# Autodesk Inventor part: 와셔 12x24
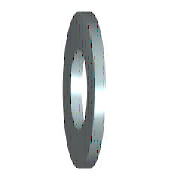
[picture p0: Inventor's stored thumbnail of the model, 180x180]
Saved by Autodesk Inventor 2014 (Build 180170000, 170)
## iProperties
IsCustomPart: 1
Created: 2012-02
Part Number: 와셔 12x24
Material: 스테인리스강
Description: 평면 와셔
Document SubType Name: Modeling
Standard: KS B 1326
Designer: mduedu
Standards Organization: KS
Language: ko-KR
Size Designation: 12x24
Categories: <MemberInstance><Categories><Category DisplayName="조임쇠" InternalName="e4da775c-781d-43d5-af7c-5136215cf5a6" Mnemonic="FSTN"><Category DisplayName="와셔" InternalN
Density: 1 g/cm^3
Appearance: 파란색 - 벽 페인트 - 광택
Author: mduedu
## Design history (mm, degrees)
sketch "스케치"
  geometry: C1 r 12 at (0, 0); C2 r 6.5 at (0, 0); 1 further point
  constraints: 2 centre point, 2 coincident
  dimensions: "d0" = 13 diameter of C2 (= SD1); "d1" = 24 diameter of C1 (= SD2)
extrude "본체" new body sketch "스케치" distance "d2" = 2.5 (= SD); taper "d3" = 0 deg
workaxis "Work Axis1"
workplane "Work Plane1"
body "Solid1"
other parameters: "SD1" = 13 [user parameter; used in 1 equation term], "SD2" = 24 [user parameter; used in 1 equation term], "SD" = 2.5 [user parameter; used in 1 equation term], "d4" = 0, "d5" = 0, "d6" = 0, "d7" = 0, "NND" = 12 [user parameter]
